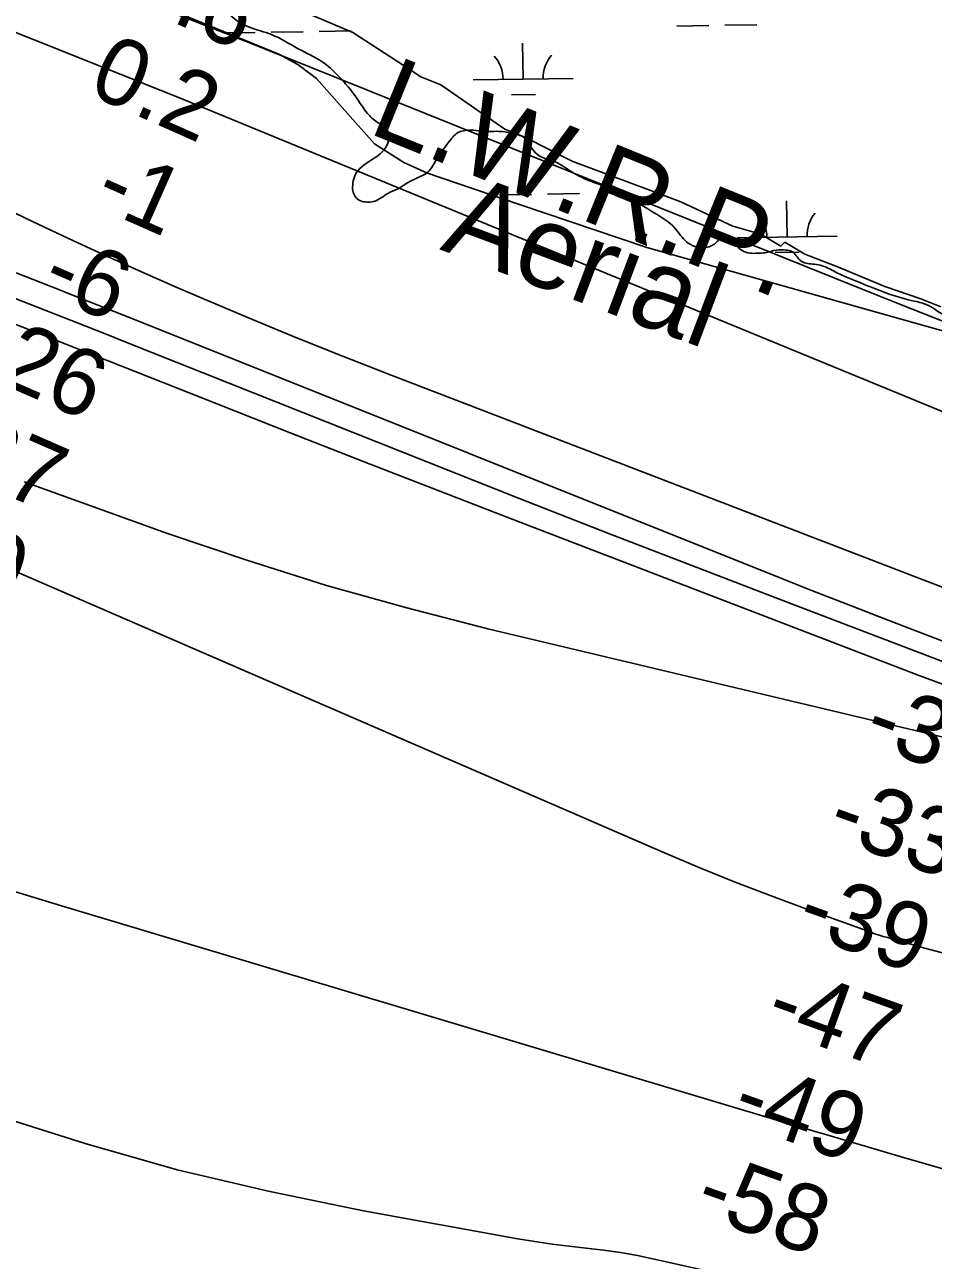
# Model space of a CAD drawing. Extents: x 3807117 to 3845308, y 337856 to 363736.
# Drawn here: x 3814255 to 3815164, y 353542 to 354778 of the extents above; entities that cross this region are included whole.
import ezdxf

# ---------------------------------------------------------------- set-up
doc = ezdxf.new("R2010")
doc.units = 0
for name, color, linetype in [('V-RIVR-EDGE', 7, 'Continuous'), ('V-RIVR-IDEN', 7, 'Continuous'), ('V-RIVR-RANG', 7, 'Continuous'), ('V-SITE-VEGE', 7, 'Continuous'), ('V-TOPO-DPTH', 7, 'Continuous'), ('V-TOPO-MAJR', 7, 'Continuous'), ('V-TOPO-MINR', 7, 'Continuous'), ('V-TOPO-WATR', 7, 'Continuous'), ('V-TOPO-WATR-IDEN', 7, 'Continuous'), ('V-WETL-SWMP', 7, 'Continuous')]:
    doc.layers.add(name, color=color, linetype=linetype)

msp = doc.modelspace()

# ---------------------------------------------------------------- linework, layer by layer
at = {"layer": 'V-RIVR-EDGE'}
msp.add_spline([(3811174.6, 356373.1), (3811188.7, 356370), (3811203.6, 356367.3), (3811222.1, 356356.8), (3811286.2, 356317.3), (3811338.6, 356278.8), (3811362.1, 356266.1), (3811376.1, 356260.1), (3811397.3, 356252.4), (3811428.9, 356236.1), (3811458.2, 356216.5), (3811472.2, 356207.9), (3811493.5, 356193.8), (3811502, 356194.7), (3811509.7, 356201), (3811518.8, 356201.5), (3811535.5, 356195.1), (3811546.8, 356183.3), (3811549.5, 356172.5), (3811555.8, 356158.4), (3811561.2, 356151.2), (3811563.9, 356150.7), (3811570.7, 356164.3), (3811577, 356167), (3811587, 356165.6), (3811593.3, 356157.4), (3811593.3, 356147.9), (3811590.5, 356127.6), (3811588.2, 356117.6), (3811588.2, 356110.9), (3811591.8, 356109.5), (3811595.9, 356113.1), (3811603.1, 356121.7), (3811609, 356123), (3811615.4, 356120.3), (3811626.2, 356116.2), (3811633, 356116.2), (3811652.9, 356117.9), (3811659.2, 356118.4), (3811668.7, 356112.9), (3811684.5, 356097.5), (3811704.8, 356068.5), (3811718.7, 356057.6), (3811733.2, 356054.4), (3811778.4, 356035.3), (3811810.9, 356009.5), (3811826.6, 355990.9), (3811837.5, 355972.8), (3811842.9, 355966.4), (3811851, 355959.6), (3811871.8, 355949.2), (3811884.4, 355946), (3811887.6, 355947.3), (3811894.8, 355959.1), (3811900.3, 355966.8), (3811904.4, 355968.1), (3811911.1, 355967.2), (3811933.7, 355960.3), (3811953.6, 355954.9), (3811968.1, 355948), (3811975.3, 355942.2), (3811975.3, 355934), (3811973.9, 355925.4), (3811965.3, 355923.6), (3811954.9, 355917.3), (3811954.4, 355912.8), (3811954.9, 355908.7), (3811959.4, 355907.8), (3811968.9, 355908.3), (3811984.7, 355910.5), (3811997.4, 355911.8), (3812006.4, 355911.3), (3812019.5, 355907.2), (3812036.2, 355901.8), (3812052.5, 355884.5), (3812061, 355876.8), (3812080.4, 355863.7), (3812103.4, 355838.7), (3812123.3, 355824.7), (3812150.9, 355811.5), (3812172.1, 355802.9), (3812200.5, 355791), (3812223.6, 355788.3), (3812292.7, 355755.5), (3812354.5, 355719.7), (3812388.9, 355704.2), (3812435.8, 355683.3), (3812470.2, 355669.6), (3812515.8, 355647.8), (3812561.9, 355627.4), (3812619.7, 355603.3), (3812627.3, 355597.4), (3812632.3, 355581.1), (3812642.2, 355563), (3812652.1, 355554.3), (3812664.7, 355545.3), (3812680.1, 355537.5), (3812689.6, 355537.5), (3812696.4, 355540.2), (3812708.6, 355557.4), (3812712.3, 355559.2), (3812718.6, 355558.7), (3812726.3, 355555.1), (3812727.2, 355547.8), (3812725.3, 355538.3), (3812726.2, 355531.1), (3812730.7, 355527.9), (3812741.6, 355524.7), (3812757.4, 355524.7), (3812770.1, 355528.7), (3812783.2, 355531), (3812801.3, 355531.4), (3812813.9, 355528.6), (3812818, 355524.1), (3812815.2, 355510.5), (3812814.8, 355503.3), (3812822, 355495.1), (3812833.7, 355491), (3812849.5, 355489.2), (3812854.5, 355488.7), (3812866.3, 355482.4), (3812885.7, 355473.3), (3812897.9, 355471), (3812923.2, 355457.8), (3812956.1, 355437.8), (3812980.5, 355421.9), (3813004, 355411.5), (3813028.8, 355399.2), (3813057.7, 355387.4), (3813082.6, 355380.1), (3813107, 355369.2), (3813115.1, 355361.9), (3813141.7, 355342.9), (3813152.5, 355328.4), (3813174.2, 355306.2), (3813192.7, 355289.8), (3813202.6, 355284.8), (3813208.5, 355285.3), (3813218, 355288), (3813230.7, 355292.9), (3813236.6, 355293.4), (3813245.1, 355289.7), (3813263.2, 355285.6), (3813267.7, 355285.1), (3813270, 355286.9), (3813270.5, 355301), (3813271.8, 355301.9), (3813276.8, 355300), (3813295.3, 355295.5), (3813313.4, 355290), (3813325.6, 355285.9), (3813339.2, 355274.6), (3813349.1, 355266.4), (3813373.5, 355254.1), (3813384.3, 355240.1), (3813390.1, 355227.4), (3813401.4, 355221.1), (3813410, 355220.1), (3813420.9, 355220.1), (3813425.4, 355215.6), (3813431.7, 355214.6), (3813438, 355215.1), (3813453, 355219.6), (3813462.9, 355219.5), (3813469.7, 355219.5), (3813510.8, 355200.9), (3813544.2, 355185.9), (3813556.4, 355177.7), (3813570.4, 355157.8), (3813577.6, 355151), (3813584.8, 355149.2), (3813595.7, 355149.6), (3813613.3, 355148.6), (3813625.5, 355148.6), (3813631.4, 355146.8), (3813632.7, 355144.1), (3813630, 355137.3), (3813633.2, 355133.7), (3813638.6, 355130.9), (3813640.8, 355124.1), (3813644.4, 355110.1), (3813651.6, 355103.3), (3813660.2, 355098.8), (3813674.7, 355096.9), (3813690.5, 355097.3), (3813700.9, 355096), (3813718.5, 355087.8), (3813718.5, 355082.4), (3813718.5, 355076), (3813722.5, 355072.9), (3813726.6, 355072.4), (3813733.4, 355078.7), (3813743.4, 355079.6), (3813752.4, 355079.6), (3813764.1, 355077.3), (3813775.4, 355072.3), (3813796.2, 355060.9), (3813812.9, 355052.3), (3813831, 355047.3), (3813835.5, 355047.3), (3813838.7, 355050.9), (3813845.5, 355051.8), (3813851.8, 355051.7), (3813864.5, 355049), (3813875.3, 355044), (3813890.7, 355036.3), (3813893.8, 355028.6), (3813896.5, 355015), (3813904.6, 355000.1), (3813910.4, 354995.5), (3813917.7, 354994.6), (3813923.6, 354996.4), (3813934.4, 355000.9), (3813943.9, 355000.9), (3813953.9, 354998.6), (3813958.8, 354990.9), (3813962.8, 354974.1), (3813969.6, 354969.6), (3813977.7, 354966), (3813995.8, 354961.9), (3814011.6, 354955.5), (3814029.3, 354950), (3814041.9, 354949.5), (3814070.9, 354953.5), (3814078.5, 354955.3), (3814093.5, 354953), (3814098.4, 354946.7), (3814098.8, 354934.5), (3814107.4, 354925), (3814114.6, 354922.7), (3814119.6, 354917.2), (3814117.8, 354903.2), (3814122.7, 354900.9), (3814126.8, 354900.9), (3814133.1, 354905.9), (3814137.7, 354908.1), (3814144.4, 354908.1), (3814158, 354902.7), (3814167.9, 354897.7), (3814183.7, 354889), (3814191.9, 354890.8), (3814207.3, 354894.9), (3814221.7, 354895.7), (3814233.5, 354890.7), (3814249.7, 354878), (3814256, 354862.2), (3814260.5, 354852.7), (3814273.6, 354845.9), (3814287.2, 354843.6), (3814299.8, 354843.5), (3814310.2, 354847.6), (3814334.2, 354848), (3814350.9, 354846.6), (3814373.5, 354840.6), (3814395.2, 354836.1), (3814414.6, 354829.7), (3814430, 354822.4), (3814448, 354805.6), (3814462.5, 354786.2), (3814479.6, 354775.7), (3814501.8, 354768.4), (3814528.4, 354754.3), (3814552.3, 354741.2), (3814565.4, 354730.3), (3814585.3, 354707.2), (3814597.9, 354689.5), (3814607.3, 354680.9), (3814616.4, 354674.6), (3814619.1, 354666.9), (3814617.2, 354657.4), (3814585.5, 354628.1), (3814583.2, 354619.9), (3814583.2, 354612.2), (3814590, 354602.3), (3814597.2, 354600.9), (3814603.5, 354601.3), (3814618, 354609.4), (3814627.5, 354613.9), (3814642, 354622.5), (3814658.3, 354631), (3814666.5, 354643.2), (3814680.1, 354662.2), (3814689.2, 354670.8), (3814695.5, 354672.5), (3814706.4, 354672.5), (3814718.6, 354671.6), (3814729.4, 354671.6), (3814744.3, 354669.3), (3814755.2, 354664.7), (3814764.2, 354652), (3814771.4, 354646.1), (3814784, 354641.6), (3814807.1, 354628), (3814826, 354619.8), (3814850.4, 354609.8), (3814882, 354591.6), (3814905.5, 354574.4), (3814916.8, 354561.2), (3814924.5, 354556.7), (3814939.4, 354556.2), (3814948.9, 354563), (3814953, 354567.5), (3814957, 354567.5), (3814966.1, 354557.9), (3814980.1, 354549.8), (3814987.7, 354549.7), (3814995.4, 354550.2), (3815006.7, 354552.9), (3815016.2, 354552.8), (3815022.1, 354551.5), (3815030.7, 354542.4), (3815042.9, 354538.8), (3815050.6, 354537.8), (3815065.5, 354531), (3815078.6, 354525.1), (3815103, 354515.1), (3815138.6, 354503.2), (3815160.8, 354496.4), (3815178.4, 354486.9), (3815184.7, 354486.9), (3815199.7, 354490), (3815209.2, 354489.5), (3815214.6, 354486.3), (3815223.1, 354477.7), (3815225.4, 354472.7), (3815220.8, 354463.7), (3815221.3, 354456.9), (3815225.3, 354451), (3815233.5, 354451), (3815240.7, 354457.3), (3815243, 354465), (3815248.4, 354469.1), (3815256.1, 354470.9), (3815267.9, 354470.4), (3815274.7, 354467.6), (3815278.7, 354467.6), (3815285.5, 354469), (3815295, 354469.9), (3815300.4, 354464.9), (3815300.9, 354455.4), (3815302.6, 354445.9), (3815313, 354440), (3815324.3, 354437.2), (3815330.2, 354436.8), (3815338.8, 354430.9), (3815351, 354418.6), (3815355.9, 354412.3), (3815365.9, 354409.1), (3815372.2, 354409.1), (3815382.1, 354402.3), (3815391.6, 354398.2), (3815392.5, 354396.4), (3815404.7, 354395.9), (3815419.2, 354395.8), (3815436.8, 354389.5), (3815445.4, 354379.5), (3815457.5, 354368.2), (3815473.8, 354360.4), (3815487.8, 354360.4), (3815509.1, 354365.8), (3815515.4, 354368), (3815523.1, 354373.4), (3815534.4, 354377.5), (3815545.7, 354377.4), (3815556.1, 354371.1), (3815567.4, 354358.4), (3815574.6, 354351.1), (3815578.7, 354351.1), (3815582.3, 354352), (3815589.5, 354353.4), (3815597.7, 354355.2), (3815605.4, 354352.9), (3815608, 354342), (3815617.5, 354323.9), (3815625.2, 354318.5), (3815645.9, 354311.6), (3815662.7, 354310.2), (3815681.7, 354308.4), (3815700.6, 354302.9)], degree=3, dxfattribs=at)
at = {"layer": 'V-SITE-VEGE'}
for p, q in [((3814583.1, 354770.5), (3814535.1, 354790.7)), ((3814639.1, 354734.3), (3814583.1, 354770.5)), ((3814651.1, 354726.2), (3814639.1, 354734.3)), ((3814671.1, 354718.1), (3814651.1, 354726.2)), ((3814735, 354673.8), (3814671.1, 354718.1)), ((3814755, 354665.8), (3814735, 354673.8)), ((3814803, 354641.6), (3814755, 354665.8)), ((3814879.1, 354613.2), (3814803, 354641.6)), ((3814911.1, 354601.1), (3814879.1, 354613.2)), ((3814963.1, 354576.9), (3814911.1, 354601.1)), ((3814991.1, 354568.8), (3814963.1, 354576.9)), ((3815011.1, 354556.7), (3814991.1, 354568.8)), ((3815015.1, 354560.7), (3815011.1, 354556.7)), ((3815035.1, 354548.6), (3815015.1, 354560.7)), ((3815067.1, 354536.5), (3815035.1, 354548.6)), ((3815115.1, 354516.3), (3815067.1, 354536.5)), ((3815151.1, 354504.1), (3815115.1, 354516.3)), ((3815171.1, 354496), (3815151.1, 354504.1))]:
    msp.add_line(p, q, dxfattribs=at)
at = {"layer": 'V-TOPO-DPTH'}
for points in [[(3817338.9, 353760.7), (3817233.7, 353780.6), (3817128.7, 353801.3), (3817023.7, 353822.5), (3816846, 353858.9), (3816830, 353862.4), (3816814.1, 353866), (3816798.2, 353869.9), (3816782.4, 353874.1), (3816573.9, 353930.8), (3816491.1, 353953.9), (3816408.5, 353977.6), (3816326.2, 354002.4), (3816244, 354027.8), (3816136.6, 354061.7), (3816108.4, 354070.7), (3816080.2, 354079.8), (3816052, 354089), (3816023.9, 354098.4), (3815282.8, 354345.9), (3814408, 354705.9), (3813687.8, 354993.4)], [(3815953.7, 353897.8), (3815699, 353980.5), (3815617.3, 354007.3), (3815535.7, 354034.5), (3815454.2, 354062.3), (3815373, 354090.5), (3815221.2, 354143.7), (3815215.9, 354145.6), (3815210.6, 354147.5), (3815205.4, 354149.5), (3815200.1, 354151.4), (3815143.4, 354173.1), (3815109.8, 354186), (3815076.3, 354199), (3815042.8, 354212.1), (3815009.4, 354225.4), (3814389.8, 354473.3), (3814353.9, 354487.6), (3814318.1, 354501.8), (3814282.2, 354516), (3814246.3, 354530.1)], [(3814246.3, 354530.1), (3814282.2, 354516), (3814318.1, 354501.8), (3814353.9, 354487.6), (3814389.8, 354473.3), (3815009.4, 354225.4), (3815042.8, 354212.1), (3815076.3, 354199), (3815109.8, 354186), (3815143.4, 354173.1), (3815200.1, 354151.4), (3815205.4, 354149.5), (3815210.6, 354147.5), (3815215.9, 354145.6), (3815221.2, 354143.7), (3815373, 354090.5), (3815454.2, 354062.3), (3815535.7, 354034.5), (3815617.3, 354007.3), (3815699, 353980.5), (3815953.7, 353897.8)], [(3814171.3, 354507.3), (3814271.7, 354468.3), (3814285.2, 354463), (3814298.7, 354457.8), (3814312.1, 354452.5), (3814325.6, 354447.1), (3814446.4, 354399.3), (3814520.3, 354370.1), (3814594.3, 354341.2), (3814668.4, 354312.4), (3814742.5, 354283.8), (3815148.5, 354127.8), (3815172.7, 354118.6), (3815196.9, 354109.4), (3815221.2, 354100.3), (3815245.5, 354091.4), (3815483.3, 354004.2), (3815570.1, 353972.8), (3815657.1, 353942.1), (3815744.3, 353912.2), (3815831.8, 353882.8)], [(3815831.8, 353882.8), (3815744.3, 353912.2), (3815657.1, 353942.1), (3815570.1, 353972.8), (3815483.3, 354004.2), (3815245.5, 354091.4), (3815221.2, 354100.3), (3815196.9, 354109.4), (3815172.7, 354118.6), (3815148.5, 354127.8), (3814742.5, 354283.8), (3814668.4, 354312.4), (3814594.3, 354341.2), (3814520.3, 354370.1), (3814446.4, 354399.3), (3814325.6, 354447.1), (3814312.1, 354452.5), (3814298.7, 354457.8), (3814285.2, 354463), (3814271.7, 354468.3), (3814171.3, 354507.3)], [(3814254.5, 354321.1), (3814397.9, 354269.5), (3814477, 354242.6), (3814556.6, 354217.4), (3814637.1, 354194.9), (3814718, 354174.1), (3815180.5, 354063.9), (3815922.8, 353801.4), (3815958, 353789.2), (3815993.3, 353777.2), (3816028.8, 353765.7), (3816064.4, 353754.5), (3816102.2, 353742.8), (3816156.8, 353726.4), (3816211.6, 353710.6), (3816266.7, 353695.6), (3816321.9, 353681.2), (3816707, 353584.1), (3816722.4, 353580.3), (3816737.8, 353576.6), (3816753.3, 353573), (3816768.8, 353569.6), (3817031.5, 353512.4)], [(3817031.5, 353512.4), (3816768.8, 353569.6), (3816753.3, 353573), (3816737.8, 353576.6), (3816722.4, 353580.3), (3816707, 353584.1), (3816321.9, 353681.2), (3816266.7, 353695.6), (3816211.6, 353710.6), (3816156.8, 353726.4), (3816102.2, 353742.8), (3816064.4, 353754.5), (3816028.8, 353765.7), (3815993.3, 353777.2), (3815958, 353789.2), (3815922.8, 353801.4), (3815180.5, 354063.9), (3814718, 354174.1), (3814637.1, 354194.9), (3814556.6, 354217.4), (3814477, 354242.6), (3814397.9, 354269.5), (3814254.5, 354321.1)], [(3814206.4, 354248.3), (3814894.9, 353950), (3814930.2, 353935.1), (3814965.6, 353920.7), (3815001.3, 353906.9), (3815037.2, 353893.5), (3815101, 353870.5), (3815105.1, 353869.1), (3815109.3, 353867.7), (3815113.6, 353866.4), (3815117.8, 353865.2), (3815153.9, 353855.1), (3815176.3, 353849), (3815198.7, 353843.2), (3815221.2, 353837.6), (3815243.7, 353832.4), (3815361, 353805.8), (3815442.2, 353787.4), (3815523.5, 353769), (3815604.7, 353750.7), (3815686, 353732.3), (3815819.2, 353702.2), (3815843.1, 353696.7)], [(3815843.1, 353696.7), (3815819.2, 353702.2), (3815686, 353732.3), (3815604.7, 353750.7), (3815523.5, 353769), (3815442.2, 353787.4), (3815361, 353805.8), (3815243.7, 353832.4), (3815221.2, 353837.6), (3815198.7, 353843.2), (3815176.3, 353849), (3815153.9, 353855.1), (3815117.8, 353865.2), (3815113.6, 353866.4), (3815109.3, 353867.7), (3815105.1, 353869.1), (3815101, 353870.5), (3815037.2, 353893.5), (3815001.3, 353906.9), (3814965.6, 353920.7), (3814930.2, 353935.1), (3814894.9, 353950), (3814206.4, 354248.3)]]:
    msp.add_lwpolyline(points, dxfattribs=at)
at = {"layer": 'V-TOPO-MAJR'}
msp.add_lwpolyline([(3815903.3, 353463.8), (3815318.3, 353597.1), (3815271.4, 353608.2), (3815224.5, 353620), (3815177.9, 353632.6), (3815131.5, 353645.9), (3815053.8, 353668.8), (3815046.3, 353671), (3815038.8, 353673.2), (3815031.3, 353675.4), (3815023.9, 353677.7), (3814291.9, 353896.8), (3814256.6, 353907.5), (3814221.3, 353918.4)], dxfattribs=at)
at = {"layer": 'V-TOPO-MINR'}
for points in [[(3816051.8, 354216.4), (3815572, 354350.2), (3815528.6, 354362.6), (3815485.2, 354375.2), (3815442, 354388.2), (3815398.9, 354401.4), (3815324.4, 354424.8), (3815318.6, 354426.6), (3815312.8, 354428.6), (3815307.1, 354430.6), (3815301.3, 354432.7), (3815239.1, 354456.3), (3815202.3, 354470.4), (3815165.6, 354484.6), (3815129, 354499), (3815092.4, 354513.6), (3814510.7, 354747.7), (3814474.9, 354762), (3814439, 354776.2), (3814403, 354790.3), (3814367, 354804.2), (3813844.9, 355005.1)], [(3815857.3, 353980.3), (3815768.5, 354009.4), (3815679.8, 354038.8), (3815591.3, 354068.7), (3815503, 354099.1), (3815285.4, 354174.7), (3815256.6, 354184.8), (3815228, 354195.1), (3815199.4, 354205.7), (3815170.9, 354216.5), (3814621.4, 354427.7), (3814573.7, 354446.4), (3814526.1, 354465.4), (3814478.7, 354485), (3814431.5, 354505), (3814406.3, 354515.9), (3814371.9, 354531), (3814337.7, 354546.3), (3814303.6, 354562.1), (3814269.6, 354578.1), (3813578.3, 354909.9)], [(3815858.7, 353893.5), (3815232.7, 354119), (3815218.4, 354124.2), (3815204.1, 354129.5), (3815189.9, 354134.8), (3815175.6, 354140.2), (3815021.8, 354198.9), (3814930.7, 354233.9), (3814839.8, 354269.1), (3814748.9, 354304.7), (3814658.2, 354340.6), (3814357.7, 354460.2), (3814333, 354470), (3814308.4, 354479.8), (3814283.7, 354489.5), (3814259, 354499.2), (3813994.4, 354602.4)], [(3815953.7, 353897.8), (3815699, 353980.5), (3815617.3, 354007.3), (3815535.7, 354034.5), (3815454.2, 354062.3), (3815373, 354090.5), (3815221.2, 354143.7), (3815215.9, 354145.6), (3815210.6, 354147.5), (3815205.4, 354149.5), (3815200.1, 354151.4), (3815143.4, 354173.1), (3815109.8, 354186), (3815076.3, 354199), (3815042.8, 354212.1), (3815009.4, 354225.4), (3814389.8, 354473.3), (3814353.9, 354487.6), (3814318.1, 354501.8), (3814282.2, 354516), (3814246.3, 354530.1)], [(3815831.8, 353882.8), (3815744.3, 353912.2), (3815657.1, 353942.1), (3815570.1, 353972.8), (3815483.3, 354004.2), (3815245.5, 354091.4), (3815221.2, 354100.3), (3815196.9, 354109.4), (3815172.7, 354118.6), (3815148.5, 354127.8), (3814742.5, 354283.8), (3814668.4, 354312.4), (3814594.3, 354341.2), (3814520.3, 354370.1), (3814446.4, 354399.3), (3814325.6, 354447.1), (3814312.1, 354452.5), (3814298.7, 354457.8), (3814285.2, 354463), (3814271.7, 354468.3), (3814171.3, 354507.3)], [(3817031.5, 353512.4), (3816768.8, 353569.6), (3816753.3, 353573), (3816737.8, 353576.6), (3816722.4, 353580.3), (3816707, 353584.1), (3816321.9, 353681.2), (3816266.7, 353695.6), (3816211.6, 353710.6), (3816156.8, 353726.4), (3816102.2, 353742.8), (3816064.4, 353754.5), (3816028.8, 353765.7), (3815993.3, 353777.2), (3815958, 353789.2), (3815922.8, 353801.4), (3815180.5, 354063.9), (3814718, 354174.1), (3814637.1, 354194.9), (3814556.6, 354217.4), (3814477, 354242.6), (3814397.9, 354269.5), (3814254.5, 354321.1)], [(3815843.1, 353696.7), (3815819.2, 353702.2), (3815686, 353732.3), (3815604.7, 353750.7), (3815523.5, 353769), (3815442.2, 353787.4), (3815361, 353805.8), (3815243.7, 353832.4), (3815221.2, 353837.6), (3815198.7, 353843.2), (3815176.3, 353849), (3815153.9, 353855.1), (3815117.8, 353865.2), (3815113.6, 353866.4), (3815109.3, 353867.7), (3815105.1, 353869.1), (3815101, 353870.5), (3815037.2, 353893.5), (3815001.3, 353906.9), (3814965.6, 353920.7), (3814930.2, 353935.1), (3814894.9, 353950), (3814206.4, 354248.3)], [(3814961.2, 353526.7), (3814884.6, 353543.7), (3814867.7, 353547.1), (3814850.7, 353550.2), (3814833.7, 353552.6), (3814816.5, 353554.5), (3814799.4, 353556.4), (3814782.3, 353558.6), (3814765.2, 353561.2), (3814748.2, 353564), (3814593.9, 353592), (3814500.2, 353611.1), (3814407.3, 353633), (3814315.5, 353659.1), (3814224.4, 353687.9)]]:
    msp.add_lwpolyline(points, dxfattribs=at)
at = {"layer": 'V-TOPO-WATR'}
msp.add_lwpolyline([(3817338.9, 353760.7), (3817233.7, 353780.6), (3817128.7, 353801.3), (3817023.7, 353822.5), (3816846, 353858.9), (3816830, 353862.4), (3816814.1, 353866), (3816798.2, 353869.9), (3816782.4, 353874.1), (3816573.9, 353930.8), (3816491.1, 353953.9), (3816408.5, 353977.6), (3816326.2, 354002.4), (3816244, 354027.8), (3816136.6, 354061.7), (3816108.4, 354070.7), (3816080.2, 354079.8), (3816052, 354089), (3816023.9, 354098.4), (3815282.8, 354345.9), (3814408, 354705.9), (3813687.8, 354993.4)], dxfattribs=at)
at = {"layer": 'V-WETL-SWMP'}
for p, q in [((3814255, 354853.2), (3814509.2, 354748.7)), ((3814907.2, 354776.9), (3814939.2, 354777.4)), ((3814955.2, 354777.7), (3814987.2, 354778.1)), ((3814456.9, 354770.2), (3814485.4, 354770.6)), ((3814501.4, 354770.9), (3814533.4, 354771.3)), ((3814549.4, 354771.6), (3814581.4, 354772.1)), ((3814753.4, 354723.9), (3814752.9, 354759.9)), ((3814509.2, 354748.7), (3814528, 354738.4)), ((3814528, 354738.4), (3814546.8, 354724.6)), ((3814546.8, 354724.6), (3814572.4, 354695.4)), ((3814703.4, 354723.1), (3814803.4, 354724.6)), ((3814741.7, 354708.3), (3814765.7, 354708.6)), ((3814572.4, 354695.4), (3814604.9, 354659.2)), ((3814604.9, 354659.2), (3814634, 354640.3)), ((3814634, 354640.3), (3814657.9, 354629.9)), ((3814657.9, 354629.9), (3814748.7, 354598.7)), ((3814729.8, 354608.1), (3814761.8, 354608.6)), ((3814777.7, 354608.8), (3814809.7, 354609.3)), ((3815017.3, 354566), (3815016.7, 354602)), ((3814748.7, 354598.7), (3814877.1, 354555.4)), ((3814967.3, 354565.2), (3815067.3, 354566.7)), ((3814877.1, 354555.4), (3815567.2, 354361)), ((3815005.5, 354550.4), (3815029.5, 354550.7))]:
    msp.add_line(p, q, dxfattribs=at)
for centre, start, end in [((3814698.2, 354723.5), 0.0865, 41.6302), ((3814808.7, 354725.2), 140.0865, 181.6302), ((3814962, 354565.6), 0.0865, 41.6302), ((3815072.5, 354567.3), 140.0865, 181.6302)]:
    msp.add_arc(centre, 35.2, start, end, dxfattribs=at)

# ---------------------------------------------------------------- texts
at = {"layer": 'V-RIVR-IDEN'}
msp.add_text('Aerial ', height=83, rotation=339.4013, dxfattribs=at).set_placement((3814669.2, 354553.7))
at = {"layer": 'V-RIVR-RANG'}
for s, rotation, p in [('5.6', 336.0783, (3814354.9, 354802.1)), ('0.2', 336.0783, (3814316.3, 354709.9)), ('-1', 336.0783, (3814321.7, 354598)), ('-6', 336.3631, (3814268.7, 354511.9)), ('-26', 336.3631, (3814198.9, 354433.3)), ('-27', 336.3631, (3814158.3, 354341.9)), ('-40', 336.3631, (3814120.4, 354249.3)), ('-30', 340.2026, (3815091.3, 354060.4)), ('-33', 340.2026, (3815054.9, 353967.2)), ('-39', 340.2026, (3815024, 353872)), ('-47', 340.2026, (3814992.9, 353777)), ('-49', 340.2026, (3814959.3, 353682.8)), ('-58', 340.2026, (3814922.5, 353589.8))]:
    msp.add_text(s, height=67, rotation=rotation, dxfattribs=at).set_placement(p)
at = {"layer": 'V-TOPO-WATR-IDEN'}
msp.add_text('L.W.R.P.', height=83, rotation=337.9012, dxfattribs=at).set_placement((3814596.5, 354670.8))

doc.saveas('drawing.dxf')
